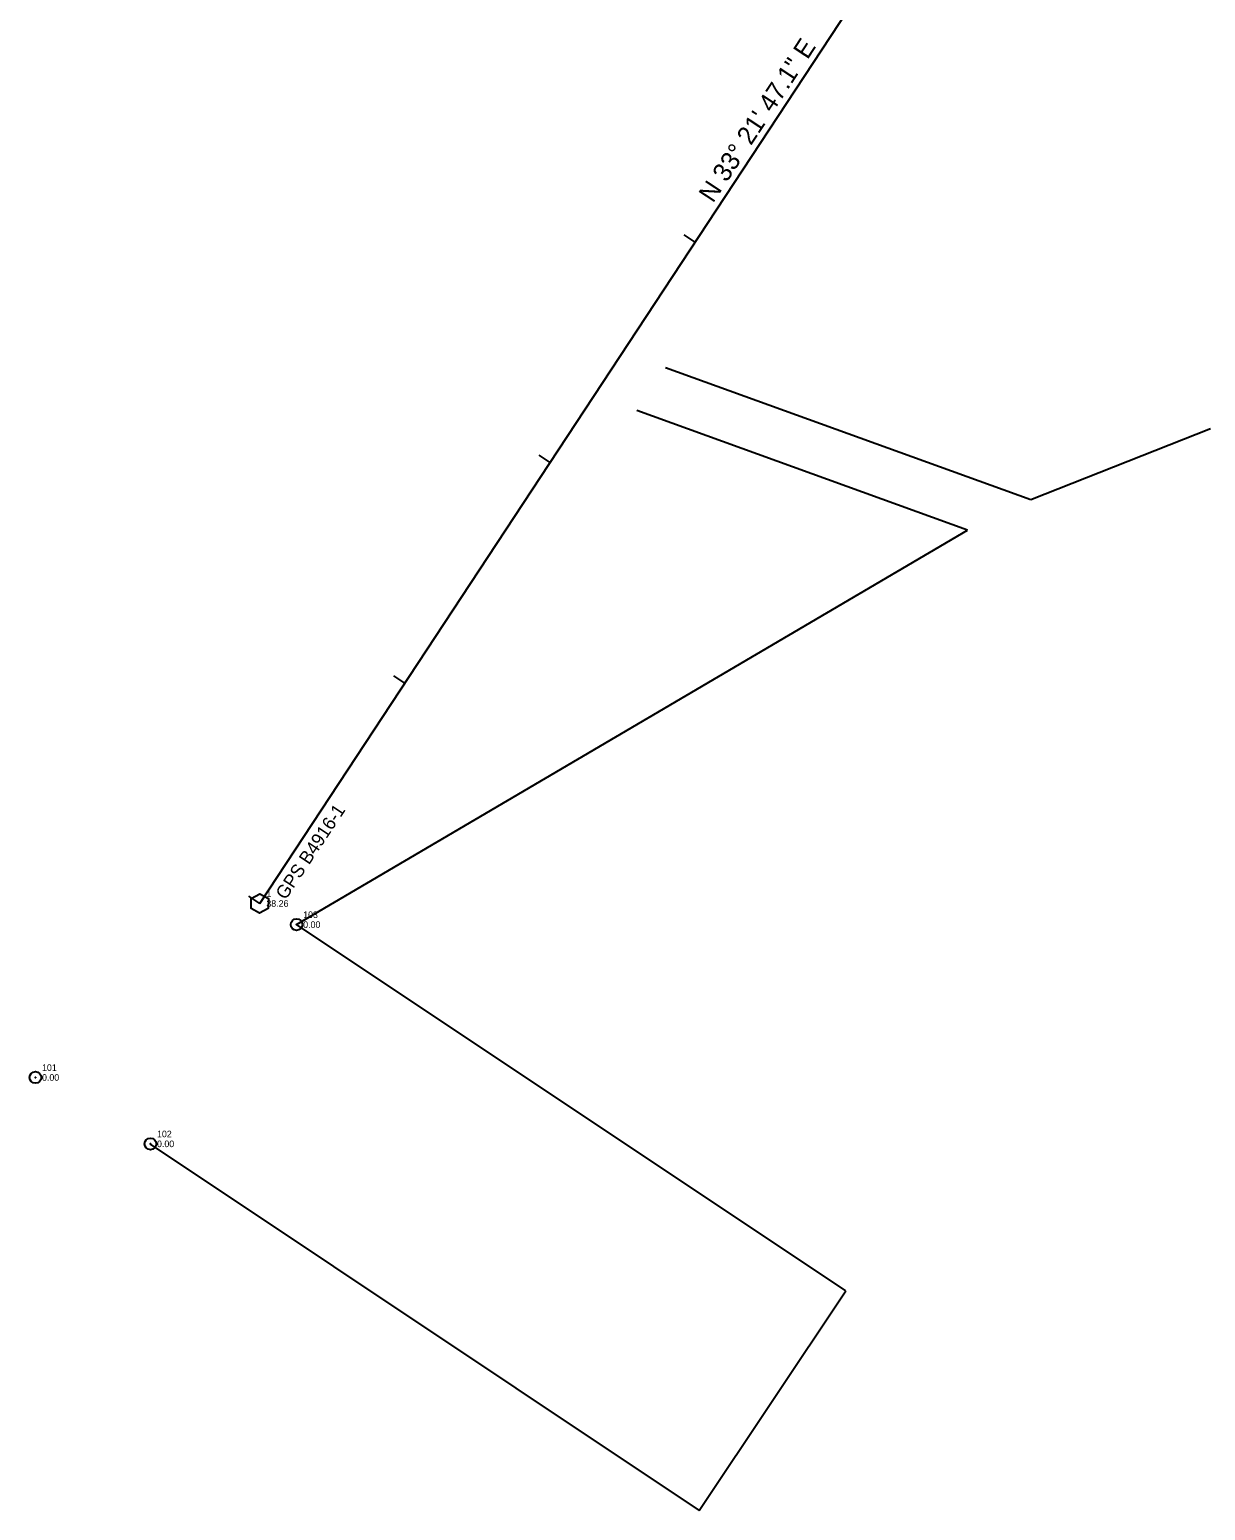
# Model space of a CAD drawing. Extents: x 2603627 to 2605187, y 896619 to 899063.
# Drawn here: x 2603627 to 2604072, y 896619 to 897180 of the extents above; entities that cross this region are included whole.
import ezdxf

# ---------------------------------------------------------------- set-up
doc = ezdxf.new("R2010")
doc.units = 0
for name, color, linetype in [('CTL GPS Vertical CELL', 7, 'Continuous'), ('CTL GPS Vertical Cogo Elevation', 7, 'Continuous'), ('CTL GPS Vertical Cogo Number', 7, 'Continuous'), ('CTL GPS Vertical Text', 7, 'Continuous'), ('Exist Horizontal Baseline Alignment', 7, 'Continuous'), ('Exist Horizontal Baseline Alignment Direction Label', 7, 'Continuous'), ('Exist Horizontal Baseline Alignment Tick small', 7, 'Continuous'), ('Exist Property Iron Pin CELL', 7, 'Continuous'), ('Scratch_Level_1', 7, 'Continuous')]:
    doc.layers.add(name, color=color, linetype=linetype)

# ---------------------------------------------------------------- blocks, each defined once
blk = doc.blocks.new('CTL GPS VERTICAL')
at = {"layer": 'CTL GPS Vertical CELL'}
blk.add_line((0, 0), (0, 0), dxfattribs=at)
blk.add_lwpolyline([(-0.065, 0.037), (0, 0.074), (0.065, 0.038), (0.064, -0.037), (-0.001, -0.074), (-0.065, -0.038)], close=True, dxfattribs=at)
blk = doc.blocks.new('EXIST PROPERTY IRON PIN')
at = {"layer": 'Exist Property Iron Pin CELL'}
for radius in [0.0441, 0.00141]:
    blk.add_circle((0, 0), radius, dxfattribs=at)

msp = doc.modelspace()

# ---------------------------------------------------------------- linework, layer by layer
at = {"layer": 'Exist Horizontal Baseline Alignment'}
msp.add_line((2603713.92, 896849.36), (2604070.2, 897390.44), dxfattribs=at)
at = {"layer": 'Exist Horizontal Baseline Alignment Tick small'}
for p, q in [((2603878.9, 897099.92), (2603874.73, 897102.67)), ((2603823.91, 897016.4), (2603819.73, 897019.15)), ((2603768.91, 896932.88), (2603764.74, 896935.63)), ((2603713.92, 896849.36), (2603709.74, 896852.11))]:
    msp.add_line(p, q, dxfattribs=at)
at = {"layer": 'Scratch_Level_1'}
for p, q in [((2603867.62, 897052.4), (2604005.96, 897002.38)), ((2603982.06, 896990.76), (2603856.8, 897036.05)), ((2604005.96, 897002.38), (2604074.06, 897029.24)), ((2603727.87, 896841.37), (2603982.06, 896990.76)), ((2603935.88, 896702.68), (2603727.87, 896841.37)), ((2603672.39, 896758.16), (2603880.4, 896619.48)), ((2603880.4, 896619.48), (2603935.88, 896702.68))]:
    msp.add_line(p, q, dxfattribs=at)

# ---------------------------------------------------------------- block references
at = {"layer": 'CTL GPS Vertical CELL', "xscale": 50, "yscale": 50}
msp.add_blockref('CTL GPS VERTICAL', (2603713.92, 896849.36), dxfattribs=at)
at = {"layer": 'Scratch_Level_1', "xscale": 50, "yscale": 50}
for p in [(2603727.87, 896841.37), (2603628.94, 896783.46), (2603672.5, 896758.32)]:
    msp.add_blockref('EXIST PROPERTY IRON PIN', p, dxfattribs=at)

# ---------------------------------------------------------------- texts
at = {"layer": 'CTL GPS Vertical Cogo Elevation'}
msp.add_text('38.26', height=2.5, dxfattribs=at).set_placement((2603716.42, 896848.11))
at = {"layer": 'CTL GPS Vertical Cogo Number'}
msp.add_text('1', height=2.5, dxfattribs=at).set_placement((2603716.42, 896851.86))
at = {"layer": 'CTL GPS Vertical Text'}
msp.add_text('GPS B4916-1', height=5, rotation=56.4094, dxfattribs=at).set_placement((2603723.73, 896850.46))
at = {"layer": 'Exist Horizontal Baseline Alignment Direction Label'}
msp.add_text('N 33%%d 21\' 47.1" E', height=7, rotation=56.6369, dxfattribs=at).set_placement((2603885.61, 897114.42))
at = {"layer": 'Scratch_Level_1'}
for s, p in [('0.00', (2603730.37, 896840.12)), ('103', (2603730.37, 896843.87)), ('101', (2603631.44, 896785.96)), ('0.00', (2603631.44, 896782.21)), ('0.00', (2603675, 896757.07)), ('102', (2603675, 896760.82))]:
    msp.add_text(s, height=2.5, dxfattribs=at).set_placement(p)

doc.saveas('drawing.dxf')
